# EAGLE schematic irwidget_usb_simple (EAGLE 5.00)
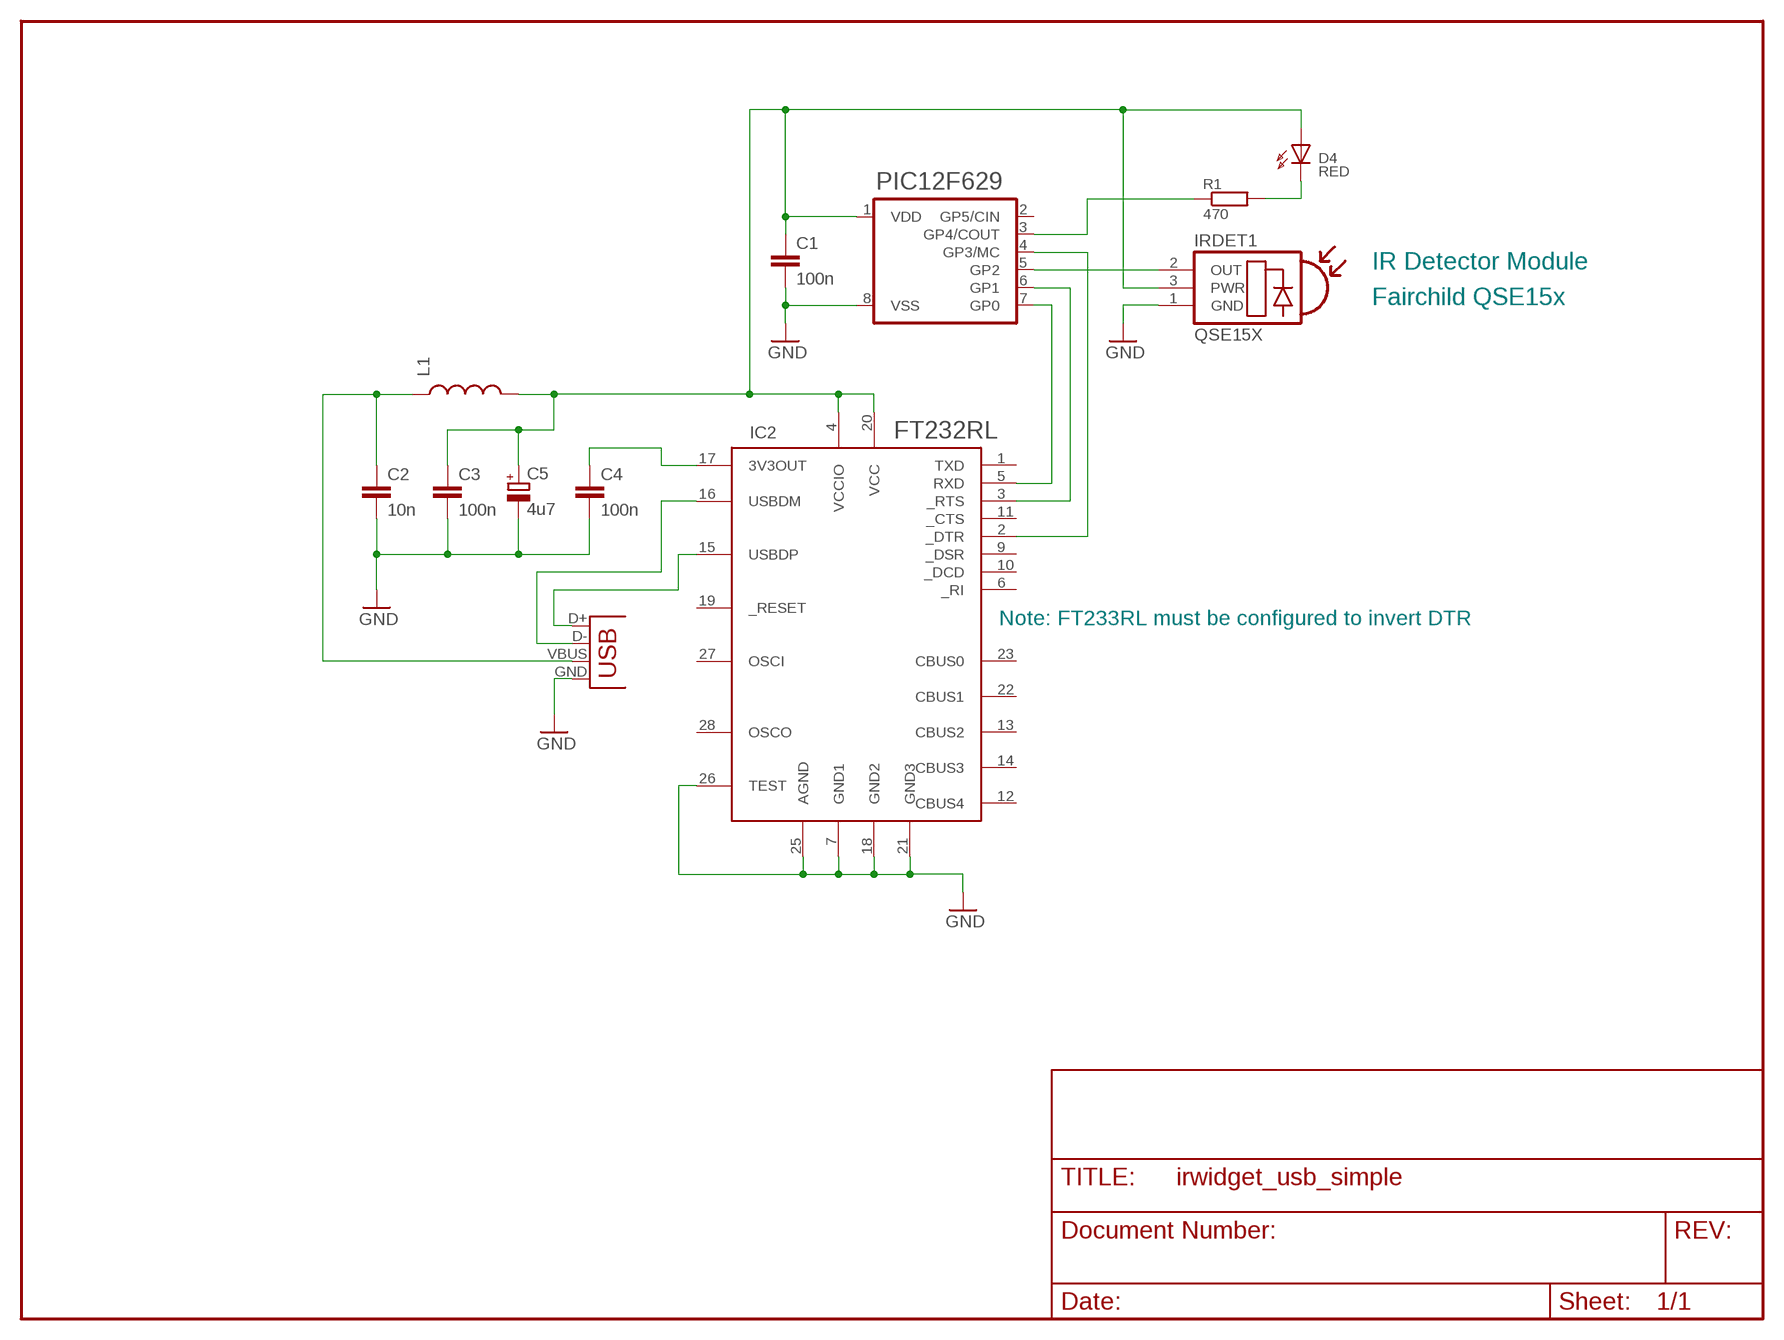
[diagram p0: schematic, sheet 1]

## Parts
C1  100n  C-EU025-025X050  [C025-025X050]
C2  10n  C-EU025-025X050  [C025-025X050]
C3  100n  C-EU025-025X050  [C025-025X050]
C4  100n  C-EU025-025X050  [C025-025X050]
C5  4u7  CPOL-EU085CS-1AW  [085CS_1AW]
D4  RED  LED5  [LED5]
IC1  12F629  12C509P  [DIL8]
IC2  FT232RL  [SSOP28DB]
IRDET1  QSE15X  [IRDET]
L1  INDUCTOR0603  [0603]
R1  470  EW30  [EW30]
X1  USBSMD  [USB-MINIB]

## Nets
GND: C1.2 C2.2 C3.2 C4.2 C5.- IC1.8(VSS) IC2.7(GND1) IC2.18(GND2) IC2.21(GND3) IC2.25(AGND) IC2.26(TEST) IRDET1.1(GND) X1.GND
N$1: C1.1 C3.1 C5.+ D4.A IC1.1(VDD) IC2.4(VCCIO) IC2.20(VCC) IRDET1.3(PWR) L1.2
N$2: IC1.5(GP2) IRDET1.2(OUT)
N$3: D4.K R1.2
N$4: IC1.4(GP3/MC) IC2.2(_DTR)
N$5: IC1.6(GP1) IC2.3(_RTS)
N$6: C4.1 IC2.17(3V3OUT)
N$10: IC2.15(USBDP) X1.D+
N$11: C2.1 L1.1 X1.VBUS
N$12: IC2.16(USBDM) X1.D-
RI: IC1.3(GP4/COUT) R1.1
RXD: IC1.7(GP0) IC2.5(RXD)
Unconnected: IC1.2(GP5/CIN) IC2.1(TXD) IC2.6(_RI) IC2.9(_DSR) IC2.10(_DCD) IC2.11(_CTS) IC2.12(CBUS4) IC2.13(CBUS2) IC2.14(CBUS3) IC2.19(_RESET) IC2.22(CBUS1) IC2.23(CBUS0) IC2.27(OSCI) IC2.28(OSCO)

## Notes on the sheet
- PIC12F629
- IR Detector Module
- Fairchild QSE15x
- FT232RL
- Note: FT233RL must be configured to invert DTR

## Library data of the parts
C1-C4 = rcl:C-EU: CAPACITOR, European symbol
C5 = rcl:CPOL-EU: POLARIZED CAPACITOR, European symbol
D4 = led:LED5
IC1 = pic:12C509P
IC2 = SparkFun:FT232RL: USB UART FT232RL 4th Generation USB UART (USB <-> Serial) Controller. Spark Fun Electronics SKU : COM-00650
IRDET1 = my_ir_mo:QSE15X
L1 = SparkFun:INDUCTOR: Inductors
R1 = my_resis:EW30
X1 = SparkFun:USB: USB Connectors USB-B-PTH is fully proven SKU : PRT-00139 USB-miniB is fully proven SKU : PRT-00587 USB-A-PCB is untested. USB-A-H is throughly reviewed, but untested. Spark Fun Electronics SKU : PRT-00437 USB-B-SMT is throughly reviewed, but untested. Needs silkscreen touching up. USB-A-S has not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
